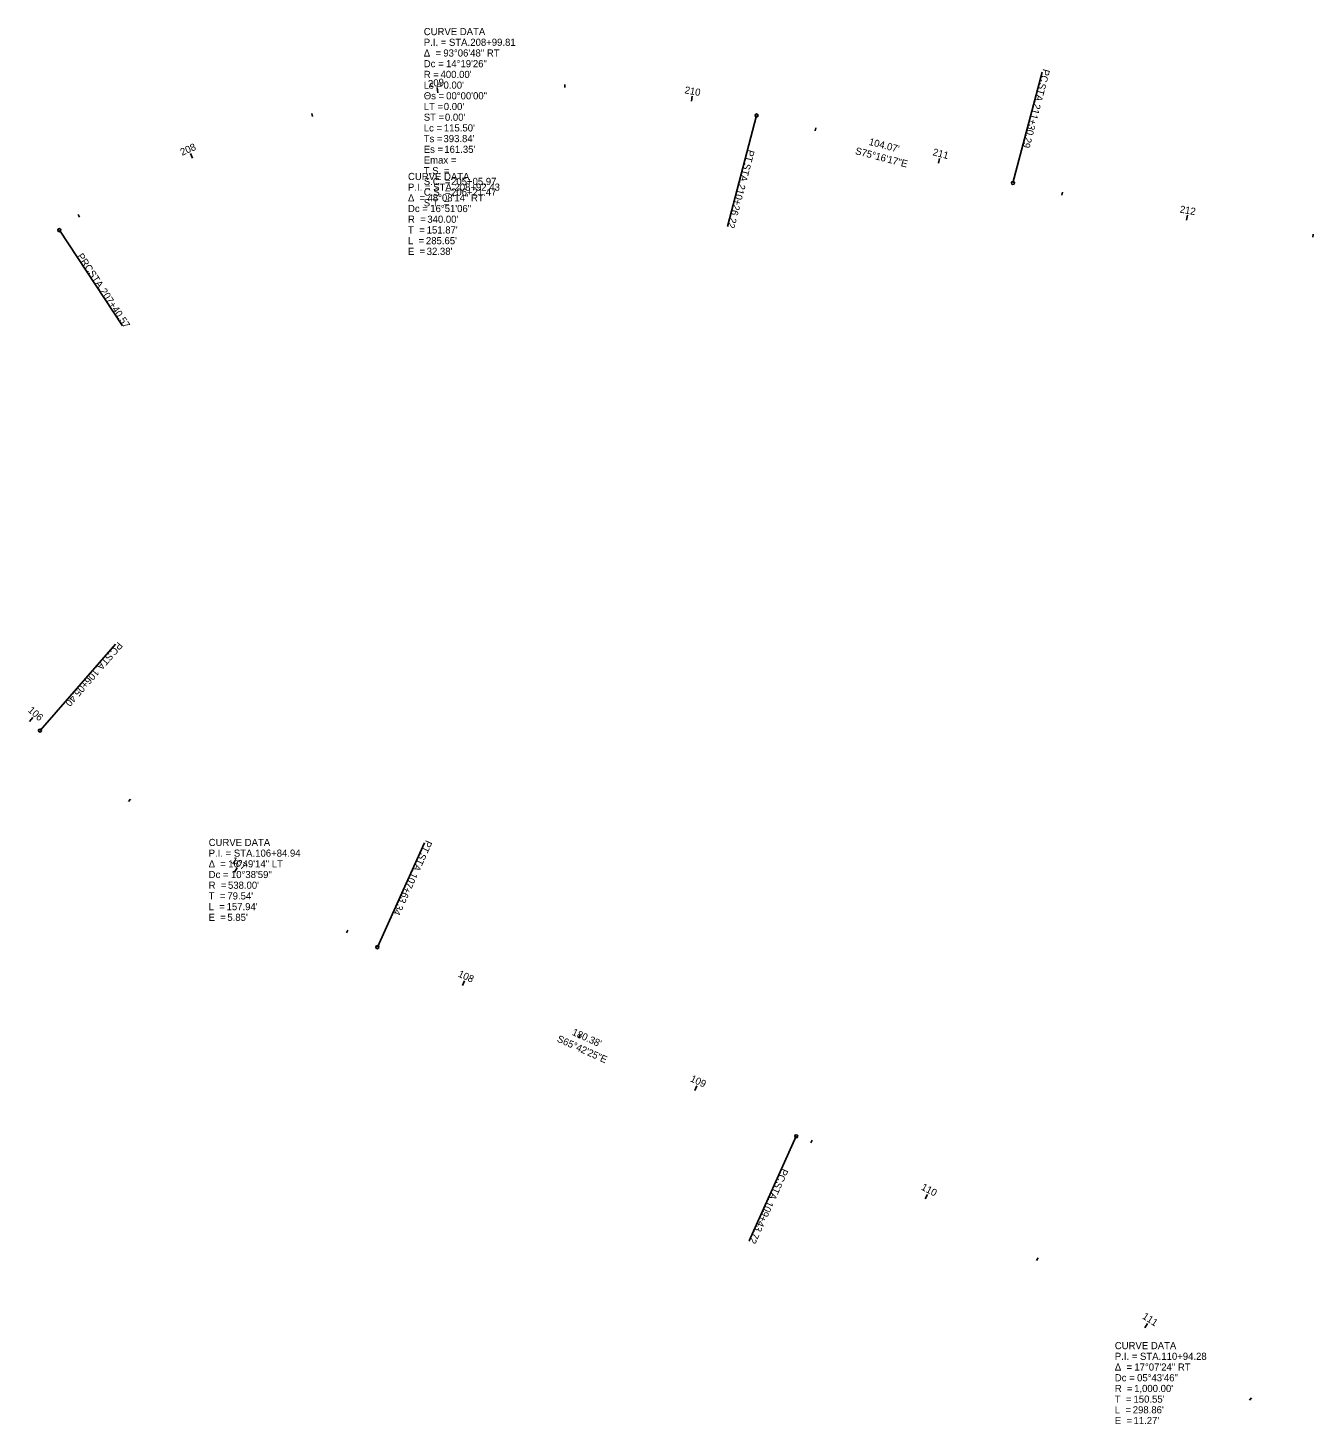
# Model space of a CAD drawing. Extents: x 1600023 to 1602131, y 285824 to 287284.
# Drawn here: x 1601112 to 1601617, y 286262 to 286810 of the extents above; entities that cross this region are included whole.
import ezdxf

# ---------------------------------------------------------------- set-up
doc = ezdxf.new("R2010")
doc.units = 0
for name, color, linetype in [('PM_P_CL_Double_Solid', 7, 'Continuous'), ('PM_P_Dotted_Line', 7, 'Continuous'), ('PM_P_Edge_Line', 7, 'Continuous'), ('PM_P_Transverse_Line', 7, 'Continuous'), ('PM_P_Yield_Line', 7, 'Continuous')]:
    doc.layers.add(name, color=color, linetype=linetype)

msp = doc.modelspace()

# ---------------------------------------------------------------- linework, layer by layer
at = {"layer": 'PM_P_CL_Double_Solid'}
for p, q in [((1601498.97, 286749.25), (1601510.41, 286792.77)), ((1601398.32, 286775.71), (1601386.88, 286732.19)), ((1601124.67, 286730.7), (1601149.45, 286693.13)), ((1601117.05, 286534.32), (1601146.64, 286568.22)), ((1601249.47, 286449.29), (1601267.99, 286490.31)), ((1601413.89, 286375.08), (1601395.37, 286334.07))]:
    msp.add_line(p, q, dxfattribs=at)
for centre in [(1601398.32, 286775.71), (1601498.97, 286749.25), (1601124.67, 286730.7), (1601117.05, 286534.32), (1601249.47, 286449.29), (1601413.89, 286375.08)]:
    msp.add_circle(centre, 0.6, dxfattribs=at)
at = {"layer": 'PM_P_Transverse_Line'}
for p, q in [((1601323.06, 286786.69), (1601323.1, 286787.89)), ((1601273.15, 286784.67), (1601272.92, 286786.65)), ((1601372.73, 286781.39), (1601373.09, 286783.36)), ((1601224.07, 286775.34), (1601223.76, 286776.5)), ((1601421.32, 286769.66), (1601421.63, 286770.82)), ((1601176.89, 286758.93), (1601176.09, 286760.77)), ((1601469.68, 286756.95), (1601470.19, 286758.88)), ((1601518.1, 286744.48), (1601518.37, 286745.65)), ((1601132.62, 286735.78), (1601131.99, 286736.8)), ((1601567.11, 286734.62), (1601567.44, 286736.6)), ((1601616.66, 286727.99), (1601616.78, 286729.18)), ((1601112.98, 286537.87), (1601114.29, 286539.38)), ((1601151.83, 286506.42), (1601152.54, 286507.38)), ((1601193.41, 286478.68), (1601194.44, 286480.4)), ((1601237.38, 286454.93), (1601237.91, 286456.01)), ((1601282.89, 286434.21), (1601283.71, 286436.03)), ((1601328.46, 286413.64), (1601328.95, 286414.73)), ((1601374.03, 286393.07), (1601374.86, 286394.89)), ((1601419.6, 286372.48), (1601420.1, 286373.57)), ((1601464.5, 286350.5), (1601465.42, 286352.27)), ((1601508.25, 286326.3), (1601508.85, 286327.33)), ((1601550.73, 286299.94), (1601551.83, 286301.61)), ((1601591.84, 286271.5), (1601592.55, 286272.46))]:
    msp.add_line(p, q, dxfattribs=at)

# ---------------------------------------------------------------- texts
at = {"layer": 'PM_P_CL_Double_Solid'}
for s, rotation, p in [('PC', 255.2715, (1601510.83, 286794.17)), (' STA. ', 255.2715, (1601509.66, 286789.74)), ('211+30.29', 255.2715, (1601507.26, 286780.6)), ('PT', 255.2715, (1601394.89, 286762.48)), (' STA. ', 255.2715, (1601393.77, 286758.21)), ('210+26.22', 255.2715, (1601391.36, 286749.07)), ('PRC', 303.4087, (1601131.46, 286720.49)), (' STA. ', 303.4087, (1601135.28, 286714.69)), ('207+40.57', 303.4087, (1601140.49, 286706.8)), ('PC', 228.8864, (1601147.65, 286569.32)), (' STA. ', 228.8864, (1601144.63, 286565.86)), ('106+05.40', 228.8864, (1601138.42, 286558.74)), (' STA. ', 245.7068, (1601266.76, 286487.48)), ('PT', 245.7068, (1601268.57, 286491.5)), ('107+63.34', 245.7068, (1601262.87, 286478.86)), ('PC', 245.7068, (1601408.34, 286362.69)), (' STA. ', 245.7068, (1601406.45, 286358.51)), ('109+43.72', 245.7068, (1601402.56, 286349.9))]:
    msp.add_text(s, height=2.8, rotation=rotation, dxfattribs=at).set_placement(p)
at = {"layer": 'PM_P_Dotted_Line'}
for s, rotation, p in [("104.07'", 345.2715, (1601442.2, 286764.22)), ("180.38'", 335.7068, (1601325.61, 286414.97))]:
    msp.add_text(s, height=2.8, rotation=rotation, dxfattribs=at).set_placement(p)
at = {"layer": 'PM_P_Edge_Line'}
for s, rotation, p in [('S75°16\'17"E', 345.2715, (1601436.85, 286760.62)), ('S65°42\'25"E', 335.7068, (1601319.74, 286412.31))]:
    msp.add_text(s, height=2.8, rotation=rotation, dxfattribs=at).set_placement(p)
at = {"layer": 'PM_P_Transverse_Line'}
for s, rotation, p in [('209', 6.5413, (1601269.57, 286786.77)), ('210', 349.6896, (1601369.89, 286784.45)), ('208', 23.393, (1601172.83, 286759.9)), ('211', 345.2715, (1601467.27, 286760.17)), ('212', 350.4996, (1601564.29, 286737.63)), ('106', 318.8864, (1601112.09, 286541.96)), ('107', 328.9612, (1601191.77, 286482.59)), ('108', 335.7068, (1601280.88, 286437.86)), ('109', 335.7068, (1601372.04, 286396.71)), ('110', 332.4824, (1601462.69, 286354.26)), ('111', 326.7529, (1601549.47, 286303.76))]:
    msp.add_text(s, height=2.8, rotation=rotation, dxfattribs=at).set_placement(p)
at = {"layer": 'PM_P_Yield_Line'}
for s, p in [('CURVE DATA', (1601267.69, 286807.25)), ('P.I. = STA. ', (1601267.69, 286803.05)), ('208+99.81', (1601285.96, 286803.05)), ('Δ  = ', (1601267.69, 286798.85)), ('93°06\'48" RT', (1601275.37, 286798.85)), ('Dc = ', (1601267.69, 286794.65)), ('R = ', (1601267.69, 286790.45)), ("400.00'", (1601274.28, 286790.45)), ('14°19\'26"', (1601276.43, 286794.65)), ('Ls = ', (1601267.69, 286786.25)), ("0.00'", (1601275.45, 286786.25)), ('Θs = ', (1601267.69, 286782.05)), ('00°00\'00"', (1601276.49, 286782.05)), ('ST = ', (1601267.69, 286773.65)), ('LT = ', (1601267.69, 286777.85)), ("0.00'", (1601275.55, 286777.85)), ("0.00'", (1601276, 286773.65)), ('Lc = ', (1601267.69, 286769.45)), ("115.50'", (1601275.57, 286769.45)), ('Ts = ', (1601267.69, 286765.25)), ("393.84'", (1601275.43, 286765.25)), ('Es = ', (1601267.69, 286761.05)), ("161.35'", (1601275.75, 286761.05)), ('T.S. = ', (1601267.69, 286752.65)), ('Emax = ', (1601267.69, 286756.85)), ('CURVE DATA', (1601261.5, 286750.4)), ('S.C. = ', (1601267.69, 286748.45)), ('205+05.97', (1601278.41, 286748.45)), ('Δ  = ', (1601261.5, 286742)), ('P.I. = STA. ', (1601261.5, 286746.2)), ('C.S. = ', (1601267.69, 286744.25)), ('48°08\'14" RT', (1601269.17, 286742)), ('206+21.47', (1601278.41, 286744.25)), ('208+92.43', (1601279.76, 286746.2)), ('Dc = ', (1601261.5, 286737.8)), ('S.T. = ', (1601267.69, 286740.05)), ('16°51\'06"', (1601270.24, 286737.8)), ('R  = ', (1601261.5, 286733.6)), ("340.00'", (1601269.08, 286733.6)), ('T  = ', (1601261.5, 286729.4)), ('L  = ', (1601261.5, 286725.2)), ("285.65'", (1601268.54, 286725.2)), ("151.87'", (1601268.84, 286729.4)), ('E  = ', (1601261.5, 286721)), ("32.38'", (1601268.84, 286721)), ('CURVE DATA', (1601183.26, 286489.01)), ('P.I. = STA. ', (1601183.26, 286484.81)), ('106+84.94', (1601201.53, 286484.81)), ('Δ  = ', (1601183.26, 286480.61)), ('16°49\'14" LT', (1601190.94, 286480.61)), ('Dc = ', (1601183.26, 286476.41)), ('10°38\'59"', (1601192, 286476.41)), ('T  = ', (1601183.26, 286468.01)), ('R  = ', (1601183.26, 286472.21)), ("79.54'", (1601190.6, 286468.01)), ("538.00'", (1601190.84, 286472.21)), ('L  = ', (1601183.26, 286463.81)), ("157.94'", (1601190.3, 286463.81)), ('E  = ', (1601183.26, 286459.61)), ("5.85'", (1601190.6, 286459.61)), ('CURVE DATA', (1601538.95, 286291.51)), ('P.I. = STA. ', (1601538.95, 286287.31)), ('110+94.28', (1601557.21, 286287.31)), ('Δ  = ', (1601538.95, 286283.11)), ('17°07\'24" RT', (1601546.62, 286283.11)), ('Dc = ', (1601538.95, 286278.91)), ('05°43\'46"', (1601547.69, 286278.91)), ('T  = ', (1601538.95, 286270.51)), ('R  = ', (1601538.95, 286274.71)), ("150.55'", (1601546.28, 286270.51)), ("1,000.00'", (1601546.53, 286274.71)), ('L  = ', (1601538.95, 286266.31)), ("298.86'", (1601545.99, 286266.31)), ('E  = ', (1601538.95, 286262.11)), ("11.27'", (1601546.29, 286262.11))]:
    msp.add_text(s, height=2.8, dxfattribs=at).set_placement(p)

doc.saveas('drawing.dxf')
